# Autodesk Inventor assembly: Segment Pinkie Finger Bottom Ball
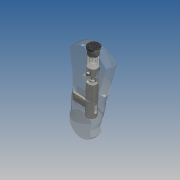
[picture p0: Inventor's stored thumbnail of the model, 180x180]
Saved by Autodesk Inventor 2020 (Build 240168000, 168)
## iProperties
Created: 2019-10
Part Number: Segment Pinkie Finger Bottom Ball
Document SubType Name: Assembly
Designer: yello
Author: yello
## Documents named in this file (7)
- C:\Users\yello\Documents\Mechanical Hand\Prototype 2 (Realistic Hand)\Segment Pinkie Finger Bottom Ball.iam
- C:\Users\yello\Documents\Mechanical Hand\Prototype 2 (Realistic Hand)\Segment Pinkie Finger Bottom.ipt
- C:\Users\yello\Documents\Mechanical Hand\Prototype 2 (Realistic Hand)\Lock.ipt
- C:\Users\yello\Documents\Mechanical Hand\Prototype 2 (Realistic Hand)\Ball.ipt
- C:\Users\yello\Documents\Mechanical Hand\Prototype 2 (Realistic Hand)\Plug 3.ipt
- C:\Users\yello\Documents\Mechanical Hand\Prototype 2 (Realistic Hand)\Push Part.ipt
- C:\Users\yello\Documents\Mechanical Hand\Prototype 2 (Realistic Hand)\Spring.ipt
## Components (7 placed, 6 different names)
1. Segment Pinkie Finger Bottom:1 — Mate:5, Mate:6, Mate:9, Mate:10, Mate:11, Mate:12, Mate:13
2. Ball:1 — Mate:6
3. Ball:2 — Mate:5
4. Push Part:1 — Mate:7, Mate:8, Mate:9
5. Lock:1 — Mate:7, Mate:8, Mate:10
6. Spring:1 — Mate:11
7. Plug 3:1 — Mate:12, Mate:13
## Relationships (9: Mate 9)
- Mate:5: Segment Pinkie Finger Bottom:1 ↔ Ball:2
- Mate:6: Segment Pinkie Finger Bottom:1 ↔ Ball:1
- Mate:7: Push Part:1 ↔ Lock:1
- Mate:8: Push Part:1 ↔ Lock:1
- Mate:9: Segment Pinkie Finger Bottom:1 ↔ Push Part:1
- Mate:10: Segment Pinkie Finger Bottom:1 ↔ Lock:1
- Mate:11: Segment Pinkie Finger Bottom:1 ↔ Spring:1
- Mate:12: Segment Pinkie Finger Bottom:1 ↔ Plug 3:1
- Mate:13: Segment Pinkie Finger Bottom:1 ↔ Plug 3:1
